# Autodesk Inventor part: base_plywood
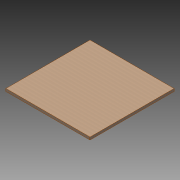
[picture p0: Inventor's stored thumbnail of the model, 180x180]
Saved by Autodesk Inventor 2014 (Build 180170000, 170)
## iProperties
Created: 2014-05
Part Number: base_plywood
Material: Maple
Document SubType Name: Modeling
Designer: t_emanb
Density: 1 g/cm^3
Appearance: Maple - Solid Natural Medium Gloss
Author: t_emanb
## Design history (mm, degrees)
sketch "Sketch1"
  geometry: L1 (0, 0)-(609.6, 0); L2 (609.6, 0)-(609.6, 609.6); L3 (609.6, 609.6)-(0, 609.6); L4 (0, 609.6)-(0, 0)
  constraints: 8 end point, 2 parallel, 1 horizontal, 1 perpendicular
  dimensions: "d0" = 609.6 distance of L1.start L1.end; "d1" = 609.6 distance of L3.end L1.start
extrude "Extrusion1" new body sketch "Sketch1" distance "d2" = 19.05; taper "d3" = 0 deg
sketch "Sketch2"
  geometry: L1 (0, 0)-(-609.6, 0) reference; L2 (-609.6, 0)-(-609.6, -609.6) reference; L3 (-609.6, -609.6)-(0, -609.6) reference; L4 (0, -609.6)-(0, 0) reference; L5 (-533.4, 0)-(-533.4, -76.2); L6 (-533.4, -76.2)-(-609.6, -76.2); L7 (-76.2, 0)-(-76.2, -76.2); L8 (-76.2, -76.2)-(0, -76.2); L9 (0, -533.4)-(-76.2, -533.4); L10 (-76.2, -533.4)-(-76.2, -609.6); L11 (-609.6, -533.4)-(-533.4, -533.4); L12 (-533.4, -533.4)-(-533.4, -609.6)
  constraints: 16 end point, 8 point on line, 6 perpendicular, 4 collinear, 2 parallel
  dimensions: "d4" = 76.2 distance of L5.start L5.end; "d5" = 76.2 distance of L5.end L6.end; "d6" = 76.2 distance of L11.end L12.end; "d7" = 76.2 distance of L7.end L8.end
extrude "Extrusion2" cut sketch "Sketch2" stored distance "d8" = 19.05; taper "d9" = 0 deg
body "Solid1"
